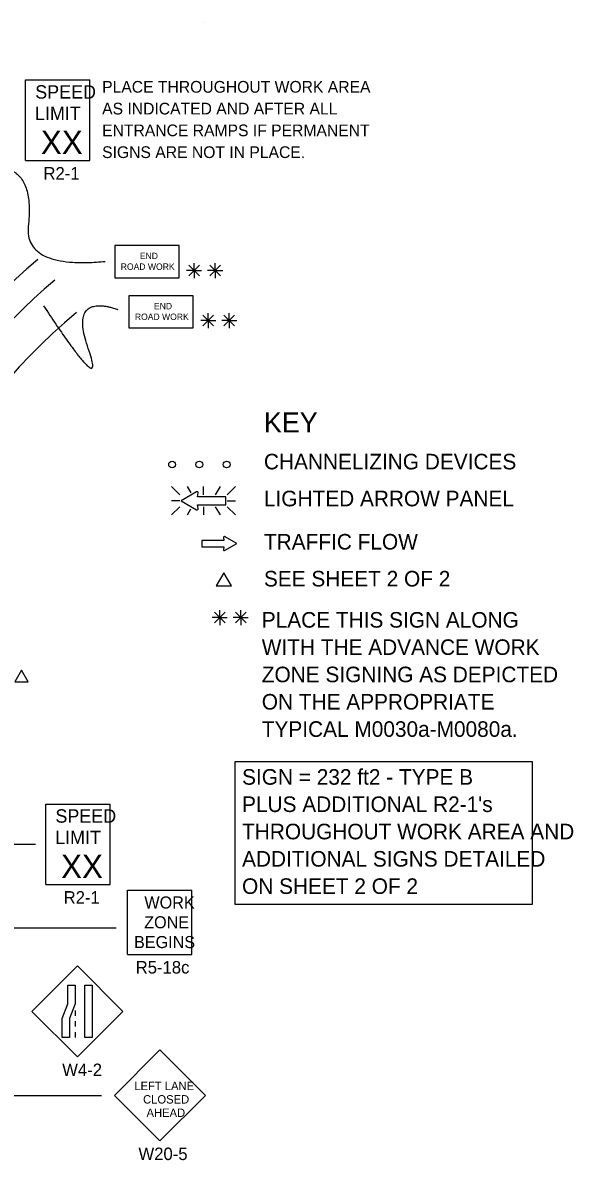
# Model space of a CAD drawing. Extents: x 16476 to 18475, y 6827 to 8243.
# Drawn here: x 17109 to 17438, y 7560 to 8239 of the extents above; entities that cross this region are included whole.
import ezdxf

# ---------------------------------------------------------------- set-up
doc = ezdxf.new("R2010")
doc.units = 0
for name, color, linetype in [('ALI_LEGAL_EX', 7, 'Continuous'), ('MT_SCRATCH_LEVEL_E', 7, 'Continuous'), ('PAVT_EDGE_EX', 7, 'Continuous'), ('TRAFFIC_SIGNS_PR', 7, 'Continuous'), ('TYPICAL_TEXT_DIMEN_EX', 7, 'Continuous'), ('TYPICAL_TEXT_DIMEN_PR', 7, 'Continuous')]:
    doc.layers.add(name, color=color, linetype=linetype)

msp = doc.modelspace()

# ---------------------------------------------------------------- linework, layer by layer
at = {"layer": 'ALI_LEGAL_EX'}
msp.add_arc((17357.65, 7803.75), 340, 129.56655, 180, dxfattribs=at)
at = {"layer": 'MT_SCRATCH_LEVEL_E'}
for p, q in [((17228.79, 7931.61), (17229.11, 7929.83)), ((17236.72, 7927.98), (17229.48, 7932.09)), ((17229.11, 7929.83), (17215.85, 7929.83)), ((17215.85, 7929.83), (17215.85, 7926.09)), ((17215.85, 7926.09), (17229.11, 7926.09)), ((17229.11, 7926.09), (17228.79, 7924.31)), ((17229.48, 7923.83), (17236.72, 7927.98))]:
    msp.add_line(p, q, dxfattribs=at)
for centre, start, end in [((17229.25, 7931.68), 60.42484, 189.96381), ((17229.25, 7924.24), 170.03619, 299.77312)]:
    msp.add_arc(centre, 0.463, start, end, dxfattribs=at)
at = {"layer": 'PAVT_EDGE_EX'}
for radius in [316, 300]:
    msp.add_arc((17319.32, 7853.94), radius, 129.56655, 180, dxfattribs=at)
at = {"layer": 'TRAFFIC_SIGNS_PR'}
for p, q in [((17110.68, 8204.69), (17149.08, 8204.69)), ((17110.68, 8156.69), (17110.68, 8204.69)), ((17149.08, 8156.69), (17149.08, 8204.69)), ((17110.68, 8156.69), (17149.08, 8156.69)), ((17197.78, 7961.99), (17202.72, 7957.06)), ((17209.55, 7958.17), (17207.34, 7961.99)), ((17216.87, 7957.06), (17216.87, 7961.99)), ((17224.1, 7957.06), (17226.95, 7961.99)), ((17231.01, 7957.06), (17235.95, 7961.99)), ((17202.72, 7953.5), (17197.78, 7953.5)), ((17231.01, 7953.5), (17235.95, 7953.5)), ((17197.78, 7945.01), (17202.72, 7949.94)), ((17207.29, 7945.01), (17209.41, 7948.67)), ((17216.87, 7949.94), (17216.87, 7945.01)), ((17226.99, 7945.01), (17224.15, 7949.94)), ((17231.01, 7949.94), (17235.95, 7945.01)), ((17122.74, 7772.47), (17161.14, 7772.47)), ((17122.74, 7724.47), (17122.74, 7772.47)), ((17161.14, 7724.47), (17161.14, 7772.47)), ((17122.74, 7724.47), (17161.14, 7724.47)), ((17171.61, 7682.74), (17171.61, 7721.14)), ((17171.61, 7721.14), (17210.01, 7721.14)), ((17210.01, 7682.74), (17210.01, 7721.14)), ((17171.61, 7682.74), (17210.01, 7682.74)), ((17141.59, 7675.84), (17114.44, 7648.69)), ((17168.74, 7648.69), (17141.59, 7675.84)), ((17114.44, 7648.69), (17141.59, 7621.54)), ((17140.34, 7649.18), (17140.34, 7645.98)), ((17141.59, 7621.54), (17168.74, 7648.69)), ((17140.34, 7642.78), (17140.34, 7639.58)), ((17140.34, 7636.38), (17140.34, 7633.18)), ((17190.91, 7625.7), (17163.75, 7598.54)), ((17218.06, 7598.54), (17190.91, 7625.7)), ((17163.75, 7598.54), (17190.91, 7571.39)), ((17190.91, 7571.39), (17218.06, 7598.54))]:
    msp.add_line(p, q, dxfattribs=at)
for points in [[(17163.89, 8086.59), (17202.29, 8086.59), (17202.29, 8105.78), (17163.89, 8105.78)], [(17172.32, 8056.67), (17210.72, 8056.67), (17210.72, 8075.87), (17172.32, 8075.87)], [(17140.34, 7664.43), (17140.34, 7653.25), (17137, 7644.36), (17137, 7633.18), (17132.5, 7633.18), (17132.5, 7644.36), (17135.85, 7653.25), (17135.85, 7664.43)], [(17150.48, 7664.43), (17150.48, 7633.18), (17145.98, 7633.18), (17145.98, 7664.43)]]:
    msp.add_lwpolyline(points, close=True, dxfattribs=at)
for points in [[(17212.79, 7958.78), (17203.5, 7953.5), (17212.8, 7948.18)], [(17213.67, 7948.81), (17213.27, 7951.07), (17230.28, 7951.07), (17230.28, 7955.88), (17213.27, 7955.88), (17213.67, 7958.16)]]:
    msp.add_lwpolyline(points, dxfattribs=at)
for centre in [(17198.12, 7975.18), (17214.42, 7975.18), (17230.72, 7975.18)]:
    msp.add_circle(centre, 2, dxfattribs=at)
for centre, radius, start, end in [((17213.08, 7958.25), 0.598, 350.73078, 118.89165), ((17213.08, 7948.7), 0.597, 241.48329, 9.95933)]:
    msp.add_arc(centre, radius, start, end, dxfattribs=at)
at = {"layer": 'TYPICAL_TEXT_DIMEN_EX'}
msp.add_lwpolyline([(17235.87, 7797.84), (17413.14, 7797.84), (17413.14, 7712.52), (17235.87, 7712.52)], close=True, dxfattribs=at)
at = {"layer": 'TYPICAL_TEXT_DIMEN_PR'}
for p, q in [((17208.12, 8094.15), (17214.5, 8087.77)), ((17214.5, 8094.15), (17208.12, 8087.77)), ((17211.31, 8090.96), (17211.31, 8095.41)), ((17220.68, 8094.15), (17227.06, 8087.77)), ((17227.06, 8094.15), (17220.68, 8087.77)), ((17223.87, 8090.96), (17223.87, 8095.41)), ((17211.31, 8090.96), (17206.78, 8090.96)), ((17211.31, 8090.96), (17214.5, 8090.96)), ((17211.31, 8090.96), (17215.79, 8090.96)), ((17211.31, 8090.96), (17211.31, 8086.46)), ((17223.87, 8090.96), (17219.33, 8090.96)), ((17223.87, 8090.96), (17227.06, 8090.96)), ((17223.87, 8090.96), (17228.35, 8090.96)), ((17223.87, 8090.96), (17223.87, 8086.46)), ((17219.74, 8061.04), (17215.21, 8061.04)), ((17216.56, 8064.23), (17222.93, 8057.86)), ((17222.93, 8064.23), (17216.56, 8057.86)), ((17219.74, 8061.04), (17219.74, 8065.5)), ((17219.74, 8061.04), (17222.93, 8061.04)), ((17219.74, 8061.04), (17224.22, 8061.04)), ((17219.74, 8061.04), (17219.74, 8056.54)), ((17232.3, 8061.04), (17227.77, 8061.04)), ((17229.11, 8064.23), (17235.49, 8057.86)), ((17235.49, 8064.23), (17229.11, 8057.86)), ((17232.3, 8061.04), (17232.3, 8065.5)), ((17232.3, 8061.04), (17235.49, 8061.04)), ((17232.3, 8061.04), (17236.78, 8061.04)), ((17232.3, 8061.04), (17232.3, 8056.54)), ((17226.61, 7883.77), (17222.07, 7883.77)), ((17223.42, 7886.96), (17229.79, 7880.59)), ((17229.79, 7886.96), (17223.42, 7880.59)), ((17226.61, 7883.77), (17226.61, 7888.23)), ((17226.61, 7883.77), (17229.79, 7883.77)), ((17226.61, 7883.77), (17231.08, 7883.77)), ((17226.61, 7883.77), (17226.61, 7879.27)), ((17239.16, 7883.77), (17234.63, 7883.77)), ((17242.35, 7886.96), (17235.97, 7880.59)), ((17235.98, 7886.96), (17242.35, 7880.59)), ((17239.16, 7883.77), (17239.16, 7888.23)), ((17239.16, 7883.77), (17242.35, 7883.77)), ((17239.16, 7883.77), (17243.64, 7883.77)), ((17239.16, 7883.77), (17239.16, 7879.27)), ((17116.65, 7748.28), (17094.47, 7748.28)), ((17164.7, 7698.28), (17094.01, 7698.28)), ((17155.92, 7598.28), (17091.72, 7598.28))]:
    msp.add_line(p, q, dxfattribs=at)
for points in [[(17229, 7910.47), (17224.47, 7902.63), (17233.52, 7902.63)], [(17108.2, 7852.44), (17104.18, 7845.48), (17112.23, 7845.48)]]:
    msp.add_lwpolyline(points, close=True, dxfattribs=at)
for points in [[(17217.32, 8238.84), (17217.33, 8238.84), (17217.34, 8238.84), (17217.34, 8238.84)], [(17054.48, 8138.06), (17038.1, 8169.55), (17089.3, 8157.23), (17115.24, 8144.22), (17109.45, 8091.8), (17158.26, 8096.33)], [(17121.47, 8069.81), (17159.71, 8011.63), (17136.49, 8077.34), (17165.85, 8067.75)]]:
    msp.add_open_spline(points, degree=2, dxfattribs=at)

# ---------------------------------------------------------------- texts
at = {"layer": 'TRAFFIC_SIGNS_PR'}
for s, height, p in [('PLACE THROUGHOUT WORK AREA', 7, (17156.39, 8197.09)), ('SPEED', 8, (17116.45, 8193.55)), ('AS INDICATED AND AFTER ALL', 7, (17156.39, 8184.09)), ('LIMIT', 8, (17116.29, 8180.75)), ('ENTRANCE RAMPS IF PERMANENT', 7, (17156.39, 8171.09)), ('XX', 14.031, (17119.8, 8160.45)), ('SIGNS ARE NOT IN PLACE.', 7, (17156.39, 8158.09)), ('R2-1', 7.44, (17121.36, 8145.25)), ('END', 3.831, (17178.89, 8097.72)), ('ROAD WORK', 3.831, (17167.5, 8091.33)), ('END', 3.831, (17187.32, 8067.8)), ('ROAD WORK', 3.831, (17175.93, 8061.42)), ('SPEED', 8, (17128.5, 7761.34)), ('LIMIT', 8, (17128.34, 7748.53)), ('XX', 14.031, (17131.85, 7728.23)), ('R2-1', 7.44, (17133.41, 7713.03)), ('WORK', 7.217, (17181.61, 7710.1)), ('ZONE', 7.217, (17181.49, 7698.29)), ('BEGINS', 7.217, (17175.42, 7686.48)), ('R5-18c', 7.44, (17176.42, 7671.3)), ('W4-2', 7.44, (17132.55, 7610.1)), ('LEFT LANE', 5.001, (17175.6, 7601.69)), ('CLOSED', 5.001, (17180.84, 7593.69)), ('AHEAD', 5.001, (17182.89, 7585.69)), ('W20-5', 7.441, (17178.07, 7559.95))]:
    msp.add_text(s, height=height, dxfattribs=at).set_placement(p)
at = {"layer": 'TYPICAL_TEXT_DIMEN_EX'}
for s, height, p in [('KEY', 12, (17252.97, 7994.29)), ('CHANNELIZING DEVICES', 9.3, (17252.97, 7972.24)), ('LIGHTED ARROW PANEL', 9.3, (17252.97, 7950.19)), ('TRAFFIC FLOW', 9.3, (17252.97, 7924.39)), ('SEE SHEET 2 OF 2', 9.3, (17252.97, 7902.34)), ('PLACE THIS SIGN ALONG', 9.3, (17251.69, 7877.77)), ('WITH THE ADVANCE WORK', 9.3, (17251.69, 7861.47)), ('ZONE SIGNING AS DEPICTED', 9.3, (17251.69, 7845.17)), ('ON THE APPROPRIATE', 9.3, (17251.69, 7828.87)), ('TYPICAL M0030a-M0080a.', 9.3, (17251.69, 7812.57)), ('SIGN = 232 ft2 - TYPE B', 9.3, (17239.92, 7784.01)), ("PLUS ADDITIONAL R2-1's", 9.3, (17239.92, 7767.71)), ('THROUGHOUT WORK AREA AND', 9.3, (17239.92, 7751.41)), ('ADDITIONAL SIGNS DETAILED', 9.3, (17239.92, 7735.11)), ('ON SHEET 2 OF 2', 9.3, (17239.92, 7718.81))]:
    msp.add_text(s, height=height, dxfattribs=at).set_placement(p)

doc.saveas('drawing.dxf')
